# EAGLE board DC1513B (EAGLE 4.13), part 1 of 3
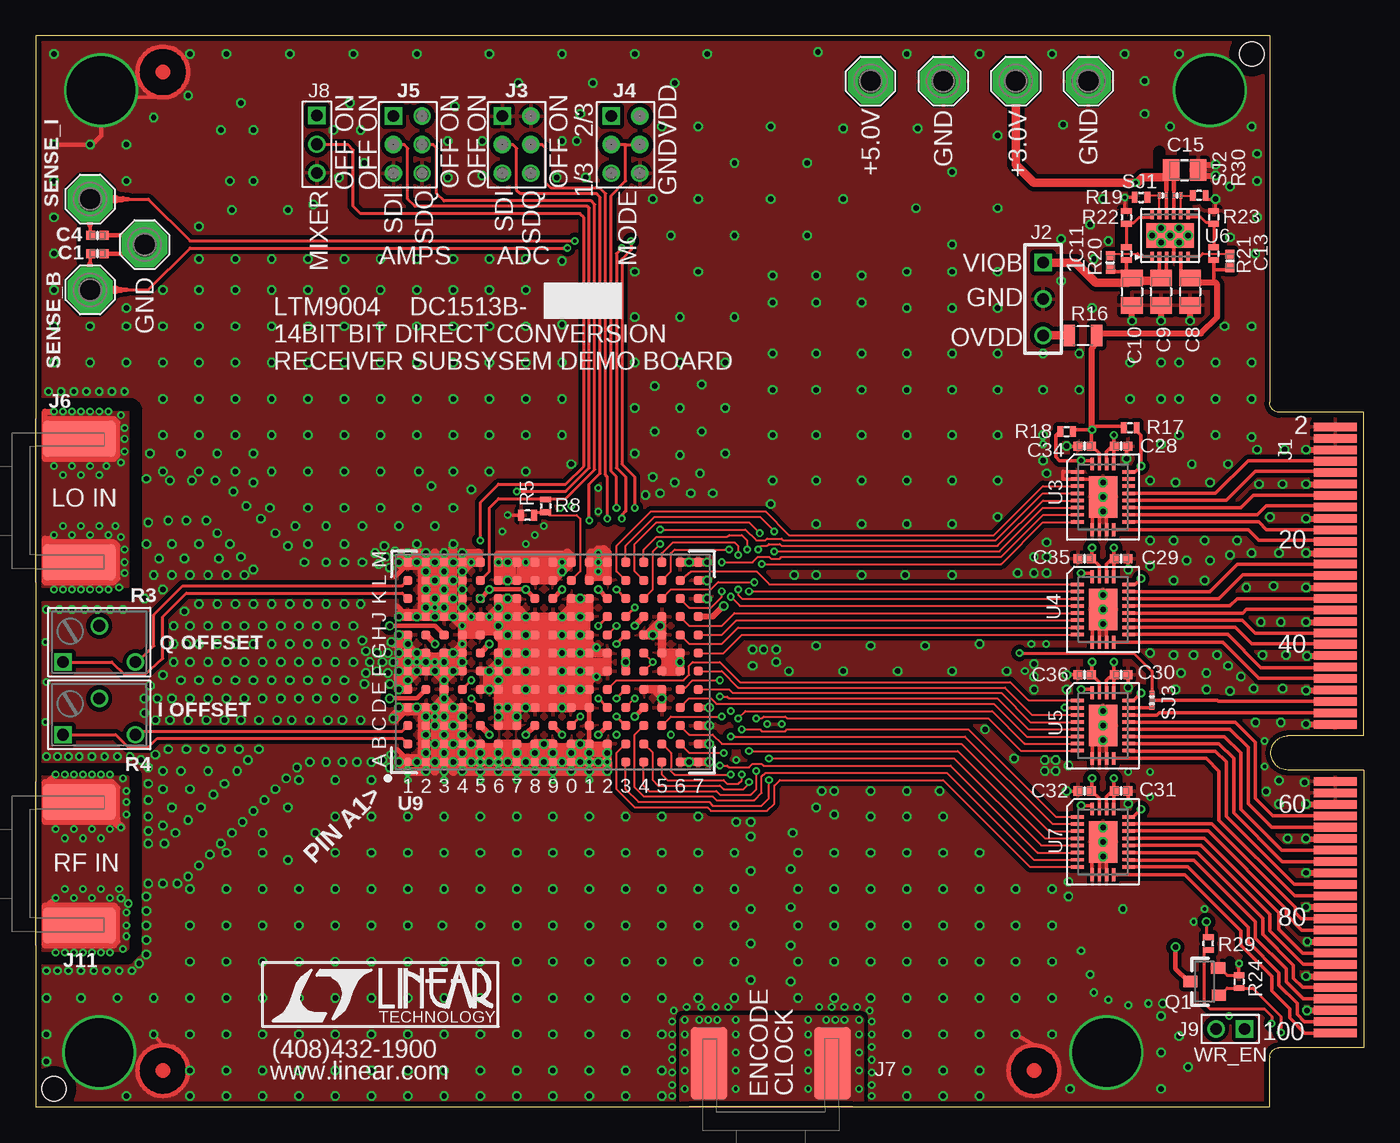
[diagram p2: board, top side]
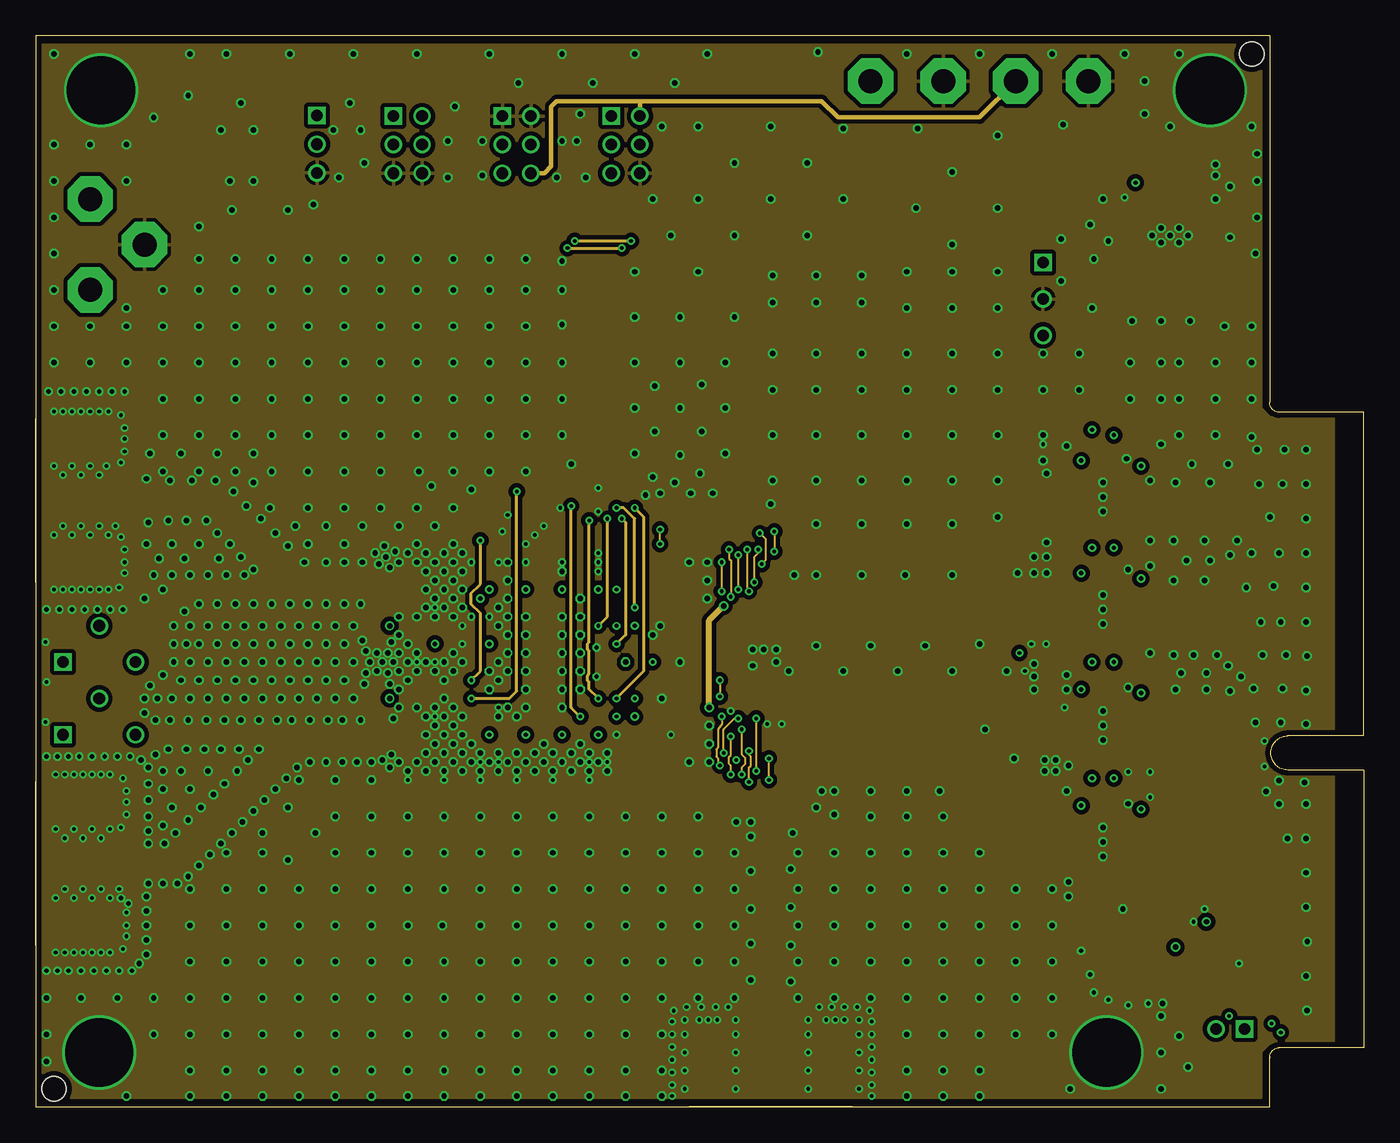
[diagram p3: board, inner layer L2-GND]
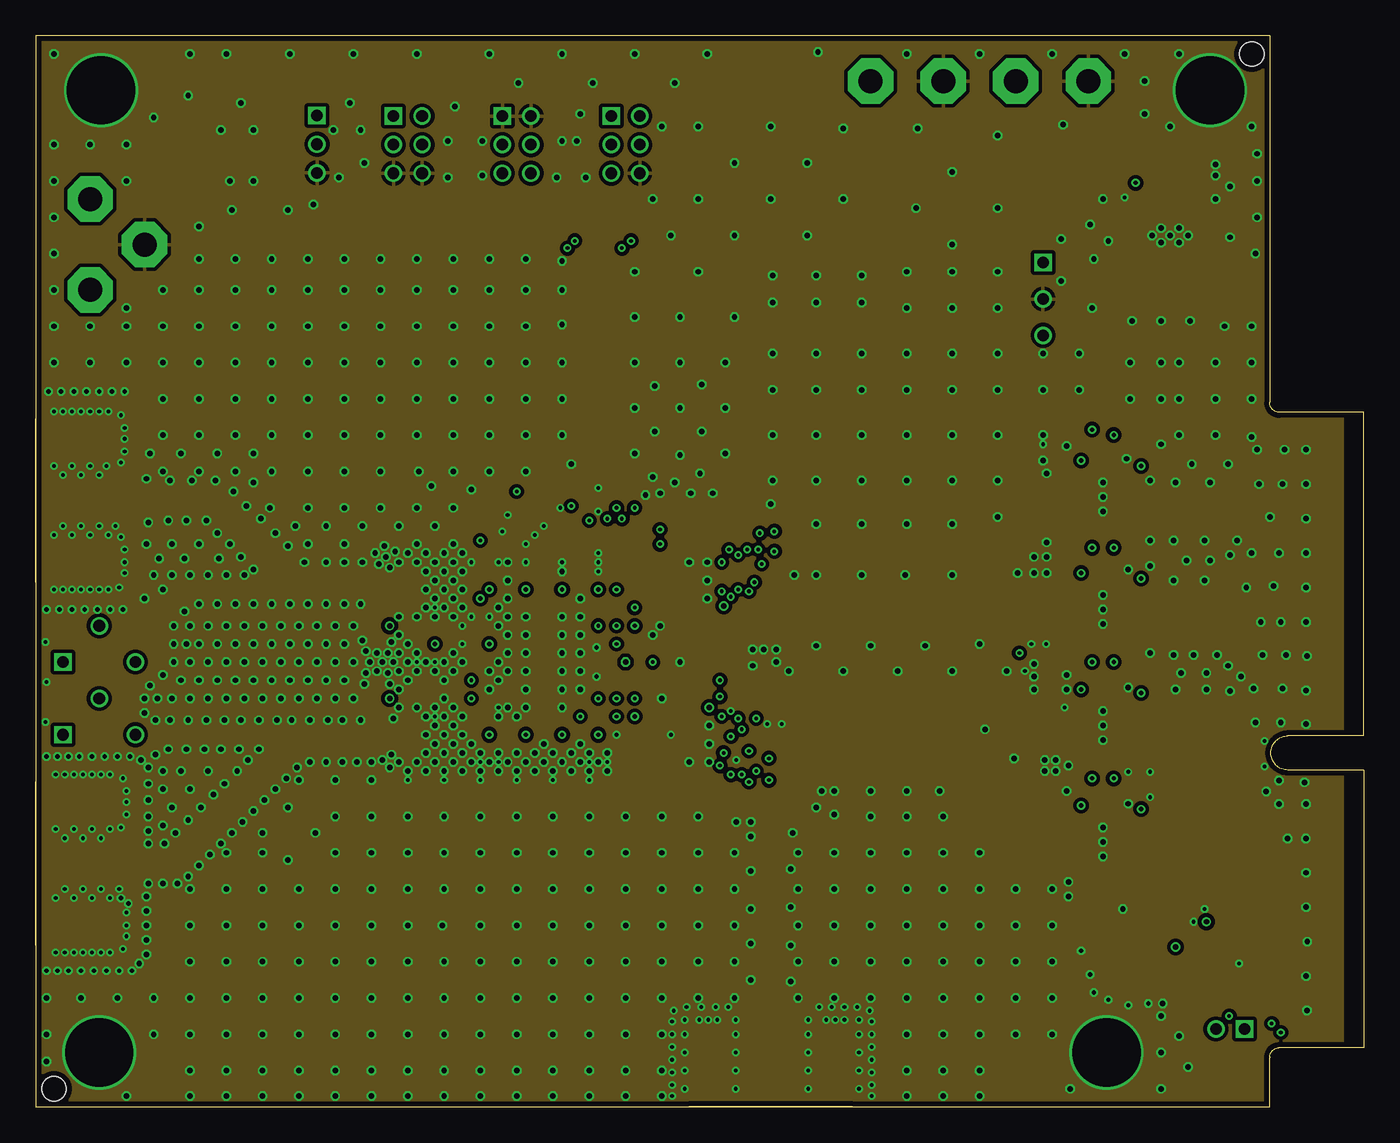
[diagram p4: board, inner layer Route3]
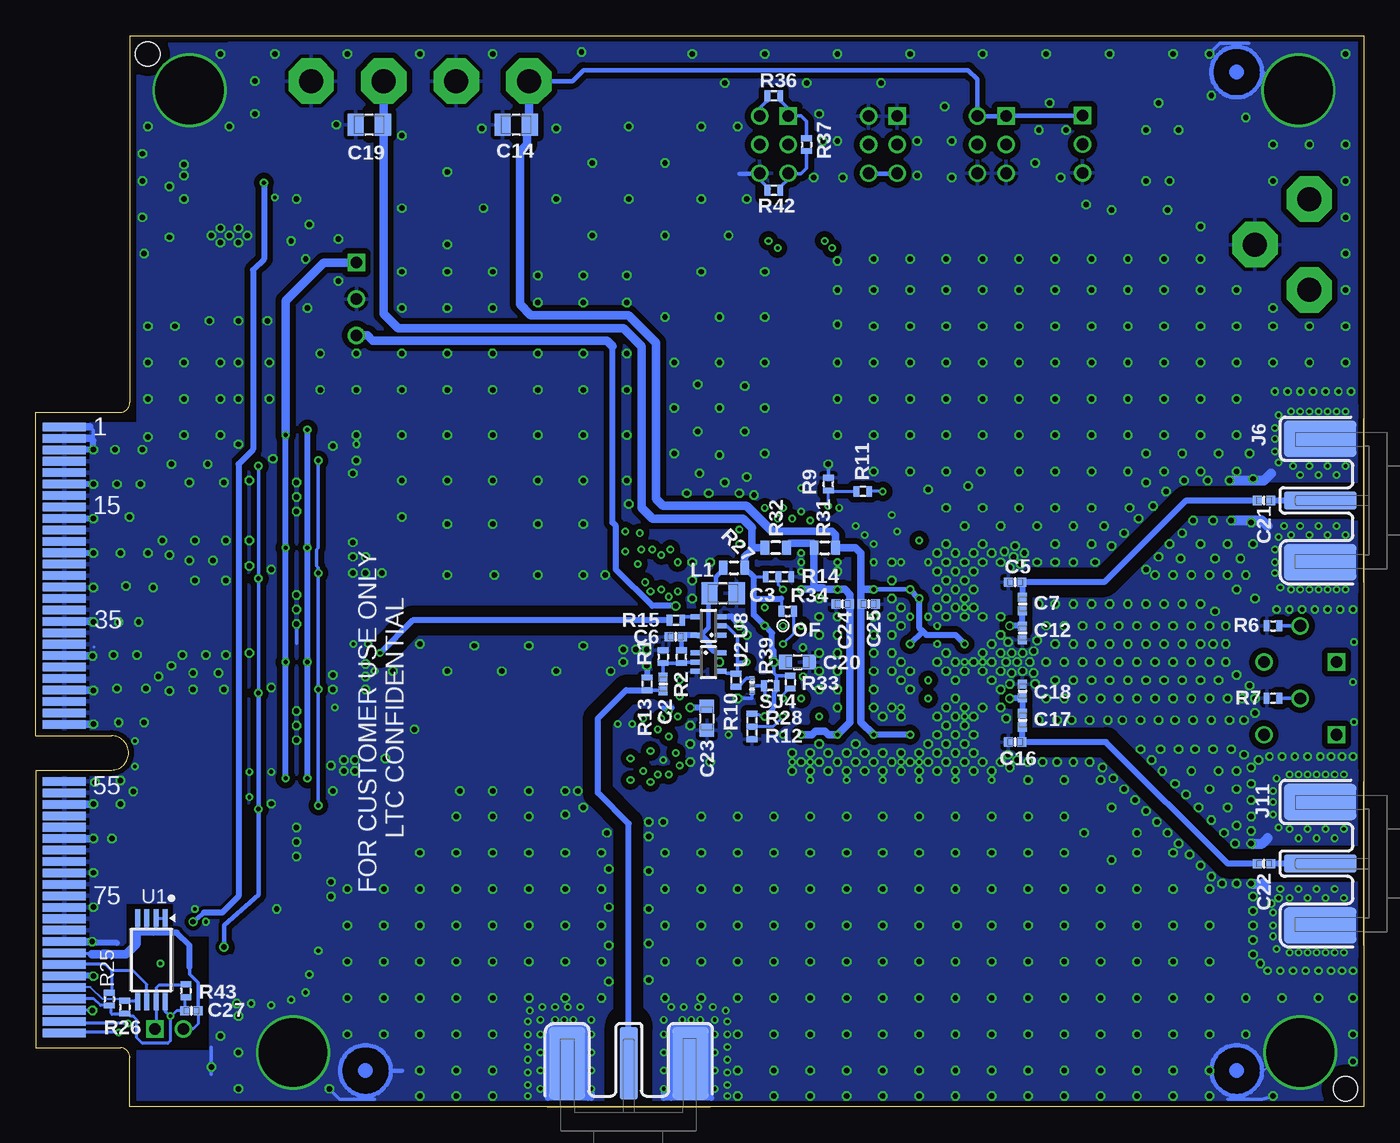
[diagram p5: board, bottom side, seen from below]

Size 92.93 x 74.93 mm. Coordinates in mm from the lower left corner, seen from the top.
Outline: 86.36,0 0,0 0,74.93 86.36,74.93 86.36,49.28
Outline: 86.36,0 86.36,3.43
Copper layers (1+2*3+16): Top 0.035mm / dielectric 0.28mm / L2-GND 0.035mm / dielectric 0.7mm / Route3 0.035mm / dielectric 0.28mm / Bottom 0.035mm
Design rules "default": minimum track width 5mil, minimum drill 10mil, track to track 5mil, track to pad 5mil, pad to pad 5mil, via to via 5mil, smd to smd 0mil, copper to edge 15mil, drill to drill 12mil, minimum pad ring 5mil, minimum via ring 0.1372mm, stop-mask expansion 3mil, vias tented up to drill 16mil, thermal gap 10mil
tKeepout: 1 lines
tRestrict: area 5.6,58.3 to 9.7,62.4; 43 lines
bRestrict: 21 lines

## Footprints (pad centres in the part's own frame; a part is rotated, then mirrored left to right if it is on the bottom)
C0402 = smd 0.635 x 0.635: 1 -0.472,0; 2 0.472,0
C0805 = smd 1.143 x 1.524: 1 -0.952,0; 2 0.952,0
C0603 = smd 0.914 x 1.016: 1 -0.837,0; 2 0.837,0
MEC8-150-02-L-D-EDGE_CONN-NEW-ORIGIN = smd 3 x 0.6 bottom: 1 3.3,22.8; 3 3.3,22; 5 3.3,21.2; 7 3.3,20.4; 9 3.3,19.6; 11 3.3,18.8; 13 3.3,18; 15 3.3,17.2; 17 3.3,16.4; 19 3.3,15.6; 21 3.3,14.8; 23 3.3,14; 25 3.3,13.2; 27 3.3,12.4; 29 3.3,11.6; 31 3.3,10.8; 33 3.3,10; 35 3.3,9.2; 37 3.3,8.4; 39 3.3,7.6; 41 3.3,6.8; 43 3.3,6; 45 3.3,5.2; 47 3.3,4.4; 49 3.3,3.6; 51 3.3,2.8; 53 3.3,2; 55 3.3,-2; 57 3.3,-2.8; 59 3.3,-3.6; 61 3.3,-4.4; 63 3.3,-5.2; 65 3.3,-6; 67 3.3,-6.8; 69 3.3,-7.6; 71 3.3,-8.4; 73 3.3,-9.2; 75 3.3,-10; 77 3.3,-10.8; 79 3.3,-11.6; 81 3.3,-12.4; 83 3.3,-13.2; 85 3.3,-14; 87 3.3,-14.8; 89 3.3,-15.6; 91 3.3,-16.4; 93 3.3,-17.2; 95 3.3,-18; 97 3.3,-18.8; 99 3.3,-19.6 | smd 3 x 0.6: 2 3.3,22.8; 4 3.3,22; 6 3.3,21.2; 8 3.3,20.4; 10 3.3,19.6; 12 3.3,18.8; 14 3.3,18; 16 3.3,17.2; 18 3.3,16.4; 20 3.3,15.6; 22 3.3,14.8; 24 3.3,14; 26 3.3,13.2; 28 3.3,12.4; 30 3.3,11.6; 32 3.3,10.8; 34 3.3,10; 36 3.3,9.2; 38 3.3,8.4; 40 3.3,7.6; 42 3.3,6.8; 44 3.3,6; 46 3.3,5.2; 48 3.3,4.4; 50 3.3,3.6; 52 3.3,2.8; 54 3.3,2; 56 3.3,-2; 58 3.3,-2.8; 60 3.3,-3.6; 62 3.3,-4.4; 64 3.3,-5.2; 66 3.3,-6; 68 3.3,-6.8; 70 3.3,-7.6; 72 3.3,-8.4; 74 3.3,-9.2; 76 3.3,-10; 78 3.3,-10.8; 80 3.3,-11.6; 82 3.3,-12.4; 84 3.3,-13.2; 86 3.3,-14; 88 3.3,-14.8; 90 3.3,-15.6; 92 3.3,-16.4; 94 3.3,-17.2; 96 3.3,-18; 98 3.3,-18.8; 100 3.3,-19.6
HDR-3X1PS-100MIL = drill 0.813 square: 1 -2.54,0 | drill 0.813 round: 2 0,0; 3 2.54,0
HDR-3X2PS-2MM = drill 0.813 square: 1 -2,-1 | drill 0.813 round: 2 -2,1; 3 0,-1; 4 0,1; 5 2,-1; 6 2,1
SMA-FEMALE-EDGE-MNT = smd 5.08 x 1.27: 1 3.048,0 | smd 5.08 x 2.54: 2 3.048,4.318; 3 3.048,-4.318 | smd 5.08 x 2.54 bottom: 4 3.048,4.318; 5 3.048,-4.318
HDR-3X1PS-2MM = drill 0.813 square: 1 0,0 | drill 0.813 round: 2 2,0; 3 4,0
HDR-2X1PS-2MM = drill 0.813 square: 1 0,0 | drill 0.813 round: 2 2,0
L0603 = smd 0.6 x 1: 1 -0.75,0; 2 0.75,0
VIA-10MIL = drill 0.254 pad 0.528 round: 1 0,0
SOT23 = smd 0.8 x 1: 1 -0.95,-1; 2 0.95,-0.95; 3 0,1
R0402 = smd 0.406 x 0.762: 1 -0.447,0; 2 0.447,0
BOURNS3262W = drill 0.813 square: 1 0,0 | drill 0.813 round: 2 2.54,2.54; 3 5.08,0
R0805 = smd 0.8 x 1.5: 1 -0.951,0; 2 0.951,0
R0603 = smd 0.6 x 1: 1 -0.75,0; 2 0.75,0
SJ1 = smd 0.279 x 0.432: 1 -0.254,0; 2 0.254,0
SJ2 = smd 0.279 x 0.432: 1 -0.508,0; 2 0,0; 3 0.508,0
TURRET_MILLMAX_2308-2 = drill 1.676 pad 3.175 octagon: 1 0,0
TSSOP8 = smd 0.35 x 1.2: 1 -0.975,-2.925; 2 -0.325,-2.925; 3 0.325,-2.925; 4 0.975,-2.925; 5 0.975,2.925; 6 0.325,2.925; 7 -0.325,2.925; 8 -0.975,2.925
SC70-5 = smd 0.35 x 0.8: 1 -0.65,-0.85; 2 0,-0.85; 3 0.65,-0.85; 4 0.65,0.85; 5 -0.65,0.85
DFN_8X4 = smd 0.9 x 0.24: 1 -2.3,-0.25; 2 -2.3,-0.75; 11 2.3,-0.75; 12 2.3,-0.25; 13 2.3,0.25; 14 2.3,0.75; 23 -2.3,0.75; 24 -2.3,0.25 | smd 0.24 x 0.9: 3 -1.75,-1.8; 4 -1.25,-1.8; 5 -0.75,-1.8; 6 -0.25,-1.8; 7 0.25,-1.8; 8 0.75,-1.8; 9 1.25,-1.8; 10 1.75,-1.8; 15 1.75,1.8; 16 1.25,1.8; 17 0.75,1.8; 18 0.25,1.8; 19 -0.25,1.8; 20 -0.75,1.8; 21 -1.25,1.8; 22 -1.75,1.8 | smd 2.9 x 2: GP 0,0
DE12 = smd 0.25 x 0.65: 1 -1.25,-1.45; 2 -0.75,-1.45; 3 -0.25,-1.45; 4 0.25,-1.45; 5 0.75,-1.45; 6 1.25,-1.45; 7 1.25,1.45; 8 0.75,1.45; 9 0.25,1.45; 10 -0.25,1.45; 11 -0.75,1.45; 12 -1.25,1.45 | smd 3.3 x 1.7: GP 0,0
LTM9005-RNDED(204_LGA) = smd 0.635 x 0.635: A1 -10.16,-6.985; A2 -8.89,-6.985; A3 -7.62,-6.985; A4 -6.35,-6.985; A5 -5.08,-6.985; A6 -3.81,-6.985; A7 -2.54,-6.985; A8 -1.27,-6.985; A9 0,-6.985; A10 1.27,-6.985; A11 2.54,-6.985; A12 3.81,-6.985; A13 5.08,-6.985; A14 6.35,-6.985; A15 7.62,-6.985; A16 8.89,-6.985; A17 10.16,-6.985; B1 -10.16,-5.715; B2 -8.89,-5.715; B3 -7.62,-5.715; B4 -6.35,-5.715; B5 -5.08,-5.715; B6 -3.81,-5.715; B7 -2.54,-5.715; B8 -1.27,-5.715; B9 0,-5.715; B10 1.27,-5.715; B11 2.54,-5.715; B12 3.81,-5.715; B13 5.08,-5.715; B14 6.35,-5.715; B15 7.62,-5.715; B16 8.89,-5.715; B17 10.16,-5.715; C1 -10.16,-4.445; C2 -8.89,-4.445; C3 -7.62,-4.445; C4 -6.35,-4.445; C5 -5.08,-4.445; C6 -3.81,-4.445; C7 -2.54,-4.445; C8 -1.27,-4.445; C9 0,-4.445; C10 1.27,-4.445; C11 2.54,-4.445; C12 3.81,-4.445; C13 5.08,-4.445; C14 6.35,-4.445; C15 7.62,-4.445; C16 8.89,-4.445; C17 10.16,-4.445; D1 -10.16,-3.175; D2 -8.89,-3.175; D3 -7.62,-3.175; D4 -6.35,-3.175; D5 -5.08,-3.175; D6 -3.81,-3.175; D7 -2.54,-3.175; D8 -1.27,-3.175; D9 0,-3.175; D10 1.27,-3.175; D11 2.54,-3.175; D12 3.81,-3.175; D13 5.08,-3.175; D14 6.35,-3.175; D15 7.62,-3.175; D16 8.89,-3.175; D17 10.16,-3.175; E1 -10.16,-1.905; E2 -8.89,-1.905; E3 -7.62,-1.905; E4 -6.35,-1.905; E5 -5.08,-1.905; E6 -3.81,-1.905; E7 -2.54,-1.905; E8 -1.27,-1.905; E9 0,-1.905; E10 1.27,-1.905; E11 2.54,-1.905; E12 3.81,-1.905; E13 5.08,-1.905; E14 6.35,-1.905; E15 7.62,-1.905; E16 8.89,-1.905; E17 10.16,-1.905; F1 -10.16,-0.635; F2 -8.89,-0.635; F3 -7.62,-0.635; F4 -6.35,-0.635; F5 -5.08,-0.635; F6 -3.81,-0.635; F7 -2.54,-0.635; F8 -1.27,-0.635; F9 0,-0.635; F10 1.27,-0.635; F11 2.54,-0.635; F12 3.81,-0.635; F13 5.08,-0.635; F14 6.35,-0.635; F15 7.62,-0.635; F16 8.89,-0.635; F17 10.16,-0.635; G1 -10.16,0.635; G2 -8.89,0.635; G3 -7.62,0.635; G4 -6.35,0.635; G5 -5.08,0.635; G6 -3.81,0.635; G7 -2.54,0.635; G8 -1.27,0.635; G9 0,0.635; G10 1.27,0.635; G11 2.54,0.635; G12 3.81,0.635; G13 5.08,0.635; G14 6.35,0.635; G15 7.62,0.635; G16 8.89,0.635; G17 10.16,0.635; H1 -10.16,1.905; H2 -8.89,1.905; H3 -7.62,1.905; H4 -6.35,1.905; H5 -5.08,1.905; H6 -3.81,1.905; H7 -2.54,1.905; H8 -1.27,1.905; H9 0,1.905; H10 1.27,1.905; H11 2.54,1.905; H12 3.81,1.905; H13 5.08,1.905; H14 6.35,1.905; H15 7.62,1.905; H16 8.89,1.905; H17 10.16,1.905; J1 -10.16,3.175; J2 -8.89,3.175; J3 -7.62,3.175; J4 -6.35,3.175; J5 -5.08,3.175; J6 -3.81,3.175; J7 -2.54,3.175; J8 -1.27,3.175; J9 0,3.175; J10 1.27,3.175; J11 2.54,3.175; J12 3.81,3.175; J13 5.08,3.175; J14 6.35,3.175; J15 7.62,3.175; J16 8.89,3.175; J17 10.16,3.175; K1 -10.16,4.445; K2 -8.89,4.445; K3 -7.62,4.445; K4 -6.35,4.445; K5 -5.08,4.445; K6 -3.81,4.445; K7 -2.54,4.445; K8 -1.27,4.445; K9 0,4.445; K10 1.27,4.445; K11 2.54,4.445; K12 3.81,4.445; K13 5.08,4.445; K14 6.35,4.445; K15 7.62,4.445; K16 8.89,4.445; K17 10.16,4.445; L1 -10.16,5.715; L2 -8.89,5.715; L3 -7.62,5.715; L4 -6.35,5.715; L5 -5.08,5.715; L6 -3.81,5.715; L7 -2.54,5.715; L8 -1.27,5.715; L9 0,5.715; L10 1.27,5.715; L11 2.54,5.715; L12 3.81,5.715; L13 5.08,5.715; L14 6.35,5.715; L15 7.62,5.715; L16 8.89,5.715; L17 10.16,5.715; M1 -10.16,6.985; M2 -8.89,6.985; M3 -7.62,6.985; M4 -6.35,6.985; M5 -5.08,6.985; M6 -3.81,6.985; M7 -2.54,6.985; M8 -1.27,6.985; M9 0,6.985; M10 1.27,6.985; M11 2.54,6.985; M12 3.81,6.985; M13 5.08,6.985; M14 6.35,6.985; M15 7.62,6.985; M16 8.89,6.985; M17 10.16,6.985
TOOLING_HOLE_0R067 = hole 1.702: 0,0

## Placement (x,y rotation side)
C1  [7]  [C0402]  4.32,59.69 0 top
C2  0.1uF  [C0402]  49.02,29.59 90 bottom
C3  4.7uF  [C0805]  44.83,35.94 0 bottom
C4  [7]  [C0402]  4.32,60.96 0 top
C5  [1]  [C0402]  24.38,36.7 180 bottom
C6  0.1uF  [C0402]  48.13,32.89 180 bottom
C7  [2]  [C0402]  23.88,35.18 270 bottom
C8  4.7uF  [C0805]  80.77,57.02 270 top
C9  4.7uF  [C0805]  78.74,57.02 270 top
C10  4.7uF  [C0805]  76.71,57.02 270 top
C11  1000pF  [C0402]  75.18,59.06 90 top
C12  [3]  [C0402]  23.88,33.15 270 bottom
C13  1000pF  [C0402]  83.57,59.18 90 top
C14  4.7uF  [C0805]  59.31,68.71 180 bottom
C15  4.7uF  [C0805]  80.39,65.53 0 top
C16  [4]  [C0402]  24.38,25.53 180 bottom
C17  [5]  [C0402]  23.88,27.05 90 bottom
C18  [6]  [C0402]  23.88,29.08 90 bottom
C19  4.7uF  [C0805]  69.6,68.71 180 bottom
C20  0.1uF  [C0603]  39.62,31.12 0 bottom
C21  100pF  [C0402]  6.99,42.42 180 bottom
C22  100pF  [C0402]  6.99,17.02 180 bottom
C23  0.1uF  [C0603]  45.97,27.18 270 bottom
C24  0.1uF  [C0402]  36.47,35.18 180 bottom
C25  0.1uF  [C0402]  34.65,35.18 0 bottom
C27  0.1uF  [C0402]  82.04,6.73 0 bottom
C28  0.1uF  [C0402]  75.95,46.23 0 top
C29  0.1uF  [C0402]  75.95,38.35 0 top
C30  0.1uF  [C0402]  75.95,30.23 0 top
C31  0.1uF  [C0402]  75.95,22.1 0 top
C32  0.1uF  [C0402]  73.41,22.1 180 top
C34  0.1uF  [C0402]  73.41,46.23 180 top
C35  0.1uF  [C0402]  73.41,38.35 180 top
C36  0.1uF  [C0402]  73.41,30.23 180 top
J1  MEC8-150-02-L-D-EDGE_CONNRE-DIM  [MEC8-150-02-L-D-EDGE_CONN-NEW-ORIGIN]  87.63,24.77 0 top
J2  TST PNTS  [HDR-3X1PS-100MIL]  70.49,56.52 270 top
J3  2802S-06G2  [HDR-3X2PS-2MM]  33.66,67.31 270 top
J4  2802S-06G2  [HDR-3X2PS-2MM]  41.28,67.31 270 top
J5  2802S-06G2  [HDR-3X2PS-2MM]  26.04,67.31 270 top
J6  [SMA-FEMALE-EDGE-MNT]  0,42.42 180 bottom
J7  [SMA-FEMALE-EDGE-MNT]  51.44,0 90 bottom
J8  3201S-03G2  [HDR-3X1PS-2MM]  19.69,69.34 270 top
J9  JMPR-2X1-PS-2MM  [HDR-2X1PS-2MM]  84.58,5.46 180 top
J11  [SMA-FEMALE-EDGE-MNT]  0,17.02 180 bottom
L1  [L0603]  44.07,37.72 0 bottom
OF  TSTPNT10MIL  [VIA-10MIL]  40.64,33.66 0 bottom
Q1  2N7002  [SOT23]  81.79,8.76 90 top
R1  1000  [R0402]  49.02,31.5 270 bottom
R2  1000  [R0402]  47.75,31.5 90 bottom
R3  BOURNS_3262W-1-103-LF  [BOURNS3262W]  1.91,31.12 0 top
R4  BOURNS_3262W-1-103-LF  [BOURNS3262W]  1.91,26.04 0 top
R5  7500  [R0402]  34.42,41.4 180 top
R6  4750  [R0402]  6.35,33.66 0 bottom
R7  4750  [R0402]  6.35,28.58 180 bottom
R8  4990  [R0402]  35.69,42.04 270 top
R9  7500  [R0402]  37.47,43.56 90 bottom
R10  33.2  [R0402]  43.94,29.85 270 bottom
R11  4990  [R0402]  35.05,43.05 180 bottom
R12  1000  [R0402]  42.8,26.16 90 bottom
R13  49.9  [R0402]  50.17,29.59 270 bottom
R14  1000  [R0402]  40.51,37.08 180 bottom
R15  33.2  [R0402]  48.13,34.04 180 bottom
R16  0  [R0805]  73.28,53.98 0 top
R17  4990  [R0402]  76.58,47.5 180 top
R18  4990  [R0402]  72.14,47.24 0 top
R19  100K  [R0402]  77.34,63.63 0 top
R20  75K  [R0402]  76.33,59.69 270 top
R21  100K  [R0402]  82.42,59.69 270 top
R22  100K  [R0402]  76.33,62.23 270 top
R23  OPT  [R0402]  82.42,62.23 270 top
R24  100K  [R0402]  84.2,8.76 270 top
R25  4990  [R0402]  87.78,7.54 270 bottom
R26  4990  [R0402]  86.69,6.99 270 bottom
R27  [8]  [R0402]  41.4,37.08 180 bottom
R28  [8]  [R0402]  42.8,27.05 90 bottom
R29  4990  [R0402]  82.04,11.43 90 top
R30  100K  [R0402]  81.41,63.75 180 top
R31  [10]  [R0603]  37.72,39.12 0 bottom
R32  [9]  [R0603]  41.15,39.12 180 bottom
R33  1000  [R0402]  40.13,29.72 270 bottom
R34  1000  [R0402]  40.31,34.67 0 bottom
R36  1000  [R0402]  41.28,70.74 0 bottom
R37  1000  [R0402]  38.99,67.31 270 bottom
R39  10K  [R0402]  41.53,29.46 180 bottom
R42  1000  [R0402]  41.28,64.14 0 bottom
R43  4990  [R0402]  82.42,8.13 270 bottom
SJ1  SOLDER_JMPR-1  [SJ1]  78.87,63.75 180 top
SJ2  SOLDER_JMPR-1  [SJ1]  79.88,63.75 0 top
SJ3  SOLDER_JMPR-2  [SJ2]  78.11,28.45 90 top
SJ4  SOLDER_JMPR-2  [SJ2]  42.8,29.46 90 bottom
TP1  TURRET0.063  [TURRET_MILLMAX_2308-2]  3.81,63.5 0 top
TP2  TURRET0.063  [TURRET_MILLMAX_2308-2]  7.62,60.33 0 top
TP4  TURRET0.063  [TURRET_MILLMAX_2308-2]  73.66,71.76 90 top
TP5  TURRET0.063  [TURRET_MILLMAX_2308-2]  68.58,71.76 0 top
TP7  TURRET0.063  [TURRET_MILLMAX_2308-2]  58.42,71.76 0 top
TP8  TURRET0.063  [TURRET_MILLMAX_2308-2]  63.5,71.76 90 top
TP12  TURRET0.063  [TURRET_MILLMAX_2308-2]  3.81,57.15 90 top
U1  24LC024-I/ST  [TSSOP8]  84.84,10.29 180 bottom
U2  NC7SVU04P5X  [SC70-5]  45.85,31.12 270 bottom
U3  FXLH42245  [DFN_8X4]  74.68,42.67 270 top
U4  FXLH42245  [DFN_8X4]  74.68,34.8 270 top
U5  FXLH42245  [DFN_8X4]  74.68,26.67 270 top
U6  LT3024IDE#PBF  [DE12]  79.38,60.96 0 top
U7  FXLH42245  [DFN_8X4]  74.68,18.54 270 top
U8  NC7SVU04P5X  [SC70-5]  45.85,33.66 90 bottom
U9  LTM9004CV  [LTM9005-RNDED(204_LGA)]  36.2,31.12 0 top
U$2  [STACKUP-4LAYER,1CORE]  not placed on the board
U$6  [TOOLING_HOLE_0R067]  85.09,73.66 0 top
U$7  [TOOLING_HOLE_0R067]  1.27,1.27 0 top
U$8  [FIDUCIAL_0R040]  8.89,72.39 0 top
U$9  [FIDUCIAL_0R040]  8.89,2.54 0 top
U$10  [FIDUCIAL_0R040]  69.85,2.54 0 top
U$11  [ARTWORK_TITLEBLOCK]  not placed on the board
U$12  [LETTER_L]  not placed on the board
U$13  [ANSI-DOC-FIELD]  not placed on the board
U$14  [REVISION-HISTORY]  not placed on the board
U$16  [FAB-NOTES-AU-THERMAL]  not placed on the board
U$17  [LT-LOGO]  15.85,5.64 0 top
